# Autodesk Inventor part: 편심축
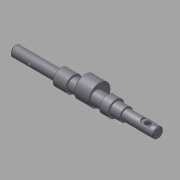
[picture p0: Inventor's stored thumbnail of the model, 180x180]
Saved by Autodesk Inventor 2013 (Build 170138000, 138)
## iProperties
Company: 한국ATC센터
Created: 2015-12
Part Number: 편심축
Document SubType Name: Modeling
Designer: mdu
Density: 7.86 g/cm^3
Mass: 248.518 g
Surface Area: 94.9962 cm^2
Volume: 31.6181 cm^3
Material: 강철, 연강
Author: mdu
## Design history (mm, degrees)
sketch "스케치1"
  geometry: L1 (-84.5, 0)-(84.5, 0); L2 (-84.5, 0)-(-84.5, 6); L3 (-84.5, 6)-(-30.5, 6); L4 (-30.5, 6)-(-30.5, 9.5); L5 (-30.5, 9.5)-(-15.5, 9.5); L6 (-15.5, 9.5)-(-15.5, 7.5); L7 (-15.5, 7.5)-(46.5, 7.5); L8 (84.5, 6)-(84.5, 0); L9 (34.5, 7.5)-(34.5, 9.5); L10 (34.5, 9.5)-(24.5, 9.5); L11 (24.5, 9.5)-(24.5, 7.5); L12 (46.5, 7.5)-(46.5, 6); L13 (46.5, 6)-(84.5, 6); 2 further points
  constraints: 26 end point, 6 parallel, 6 perpendicular, 2 point on line, 1 coincident, 1 horizontal, 1 midpoint
  dimensions: "d1" = 12 diameter of L3 L1; "d2" = 15 diameter of L7 L1; "d4" = 15 distance of L4.end L5.end; "d5" = 19 diameter of L5 L1; "d24" = 10 distance of L9.end L10.end; "d25" = 19 diameter of L10 L1; "d27" = 40 distance between parallel lines of L11 L6; "d28" = 54 distance of L2.end L3.end; "d29" = 50 distance between parallel lines of L8 L9; "d41" = 38 distance between parallel lines of L8 L12; "d42" = 12 diameter of L13 L1
revolve "회전1" stored, may be unused: angle "d6" = 90 deg
node "작업 평면1"
sketch "스케치2"
  geometry: C1 r 7.5 at (0, 0) reference; C2 r 12.5 at (0, 4.5); 1 further point
  constraints: 1 centre point, 1 vertical alignment
  dimensions: "d8" = 4.5 distance of point (0, 0) C2.centre; "d9" = 25 diameter of C2
extrude "돌출1" join sketch "스케치2" distance "d10" = 18; taper "d11" = 0 deg
chamfer "모따기1" distance "d12" = 1; stored, may be unused: second distance "d13" = 2, angle "d14" = 45 deg
chamfer "모따기2" distance "d15" = 0.5; stored, may be unused: second distance "d16" = 2, angle "d17" = 45 deg
node "작업 평면2"
sketch "스케치3"
  geometry: L1 (4, -2)-(18, -2); L2 (18, 2)-(4, 2); L3 (27, 5)-(27, -5) reference; A1 r 2 centre (18, 0) between (18, -2) and (18, 2); A2 r 2 centre (4, 0) between (4, 2) and (4, -2); 2 further points
  constraints: 4 end point, 4 point on circle, 4 tangent, 2 centre point, 1 horizontal, 1 horizontal alignment, 1 midpoint, 1 parallel
  dimensions: "d18" = 7 distance edge to line of A1 L3; "d19" = 4 distance between parallel lines of L2 L1; "d20" = 18 dimension on A1 A2
extrude "돌출2" cut sketch "스케치3" distance "d21" = 2.5; taper "d22" = 0 deg
revolve "회전2" stored, may be unused: angle "d26" = 90 deg
node "작업 평면3"
sketch "스케치4"
  geometry: L1 (44, 5)-(44, -5) reference; 2 further points
  constraints: 1 horizontal alignment
  dimensions: "d30" = 12 distance from line of point (32, 0) L1
hole "구멍1" sketch "스케치4" at (32, 0) diameter "d31" = 6; stored, may be unused: countersink angle "d35" = 90 deg, drill point angle "d37" = 118 deg; dims "d32" = 6, "d33" = 14, "d34" = 3, "d36" = 8
node "작업 평면4"
sketch "스케치5"
  geometry: C1 r 3 at (32, 0) reference; C2 r 8 at (32, 0); 2 further points
  constraints: 1 centre point, 1 coincident, 1 other
  dimensions: "d38" = 16 diameter of C2
extrude "돌출3" cut sketch "스케치5" distance "d39" = 3; taper "d40" = 0 deg
sketch "스케치6"
  geometry: L1 (-83.5, -6)-(-30.5, -6) reference; L2 (-84.5, -5)-(-84.5, 5) reference; L3 (-83.5, 6)-(-30.5, 6) reference; L4 (-62.5, 6)-(-62.5, -6); L5 (-62.5, -6)-(-61, -6); L6 (-62.5, -4.5)-(-61, -6); L7 (-62.5, -6)-(-62.5, -4.5); 2 further points
  constraints: 8 end point, 4 point on line, 2 perpendicular, 1 coincident
  dimensions: "d43" = 22 distance between parallel lines of L4 L2; "d44" = 45 deg angle of L6 L7; "d45" = 3 diameter of L5.end L4
revolve "회전3" stored, may be unused: angle "d46" = 90 deg
node "작업점1"
chamfer "모따기3" distance "d47" = 0.5; stored, may be unused: second distance "d48" = 2, angle "d49" = 45 deg
node "솔리드1"
node "투영된 루프1"
other parameters: "d7" = 8.5
